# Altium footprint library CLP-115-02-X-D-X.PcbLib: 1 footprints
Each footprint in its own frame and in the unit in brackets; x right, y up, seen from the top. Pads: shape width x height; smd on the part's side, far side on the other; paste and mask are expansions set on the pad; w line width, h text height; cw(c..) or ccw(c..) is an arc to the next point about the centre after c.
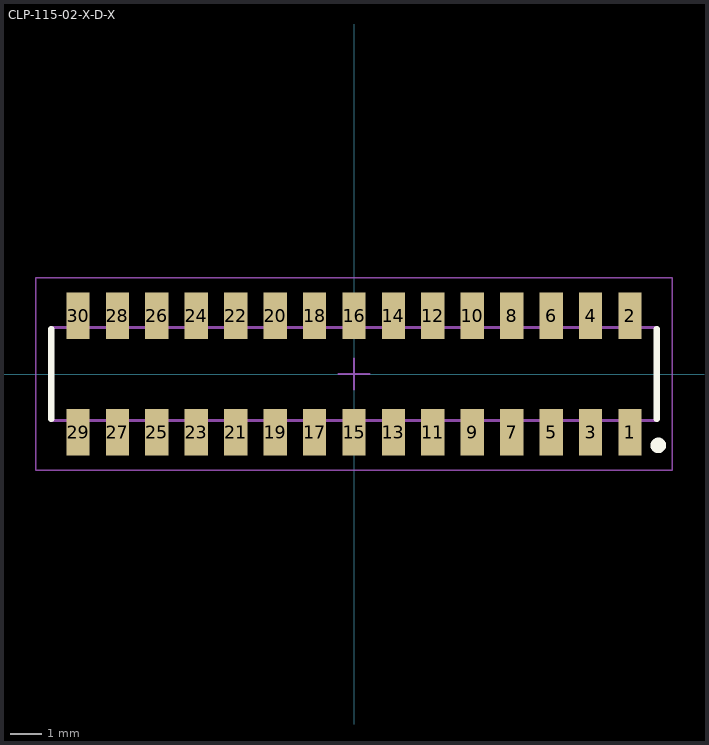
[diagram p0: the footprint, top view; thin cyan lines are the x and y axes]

## CLP-115-02-X-D-X [mm] "1.27mm pitch, 30 pin, socket strip; low profile"
height 2.26
pads (30):
  rect 0.75x1.5 smd mask+0: 1(8.89,-1.87) 2(8.89,1.87) 3(7.62,-1.87) 4(7.62,1.87) 5(6.35,-1.87) 6(6.35,1.87) 7(5.08,-1.87) 8(5.08,1.87) 9(3.81,-1.87) 10(3.81,1.87) 11(2.54,-1.87) 12(2.54,1.87) 13(1.27,-1.87) 14(1.27,1.87) 15(0,-1.87) 16(0,1.87) 17(-1.27,-1.87) 18(-1.27,1.87) 19(-2.54,-1.87) 20(-2.54,1.87) 21(-3.81,-1.87) 22(-3.81,1.87) 23(-5.08,-1.87) 24(-5.08,1.87) 25(-6.35,-1.87) 26(-6.35,1.87) 27(-7.62,-1.87) 28(-7.62,1.87) 29(-8.89,-1.87) 30(-8.89,1.87)
Top Overlay:
  circle w0.25: c9.8,-2.3 r0.125
  lines w0.2: -9.75,-1.45 -9.75,1.45 ; 9.75,-1.45 9.75,1.45
Mechanical 12:
  lines w0.001: -9.75,-1.5 -9.75,1.5 9.75,1.5 9.75,-1.5 -9.75,-1.5
Mechanical 13:
  lines w0.1: -9.75,-1.5 -9.75,1.5 9.75,1.5 9.75,-1.5 -9.75,-1.5
  text ".Designator" at 0.254,0.254 h1.52
Mechanical 15:
  lines w0.05: -0.5,0 0.5,0 ; 0,-0.5 0,0.5 ; -10.25,-3.1 -10.25,3.1 10.25,3.1 10.25,-3.1 -10.25,-3.1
